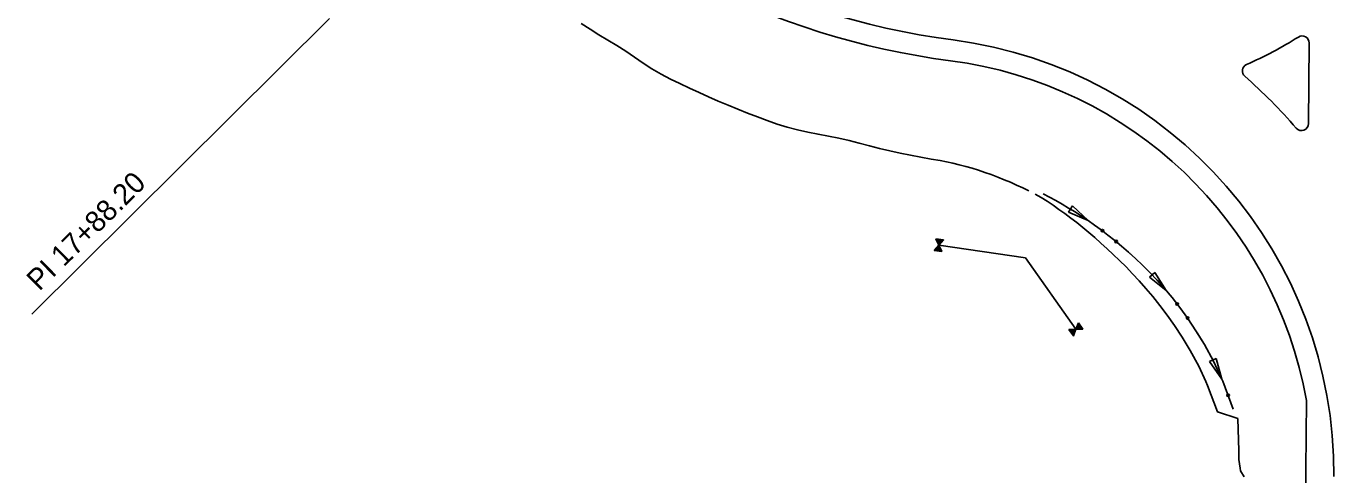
# Model space of a CAD drawing. Extents: x 1311167 to 1314552, y 2087587 to 2090602.
# Drawn here: x 1313604.5 to 1313978.4, y 2088279.1 to 2088407.4 of the extents above; entities that cross this region are included whole.
import ezdxf

# ---------------------------------------------------------------- set-up
doc = ezdxf.new("R2010")
doc.units = 0
for name, color, linetype in [('R_Shld_GR', 7, 'Continuous'), ('S_DITCHLINE', 7, 'Continuous'), ('S_DROP_INLET', 7, 'Continuous'), ('S_EDGE_CONCRETE', 7, 'Continuous'), ('S_EDGE_PAVEMENT', 7, 'Continuous'), ('S_PAVEMENT_CROWN', 7, 'Continuous')]:
    doc.layers.add(name, color=color, linetype=linetype)

msp = doc.modelspace()

# ---------------------------------------------------------------- linework, layer by layer
at = {"layer": 'R_Shld_GR'}
msp.add_lwpolyline([(1313691.22, 2088409.64), (1313606.07, 2088325.08)], dxfattribs=at)
at = {"layer": 'S_DITCHLINE'}
for p, q in [((1313903.72, 2088355.99), (1313902.57, 2088354.21)), ((1313902.57, 2088354.21), (1313908.19, 2088351.85)), ((1313908.19, 2088351.85), (1313903.72, 2088355.99)), ((1313927.27, 2088337.01), (1313925.69, 2088335.61)), ((1313925.69, 2088335.61), (1313930.47, 2088331.83)), ((1313930.47, 2088331.83), (1313927.27, 2088337.01)), ((1313944.81, 2088312.37), (1313942.89, 2088311.46)), ((1313946.42, 2088306.49), (1313944.81, 2088312.37)), ((1313942.89, 2088311.46), (1313946.42, 2088306.49))]:
    msp.add_line(p, q, dxfattribs=at)
for points in [[(1313895.28, 2088359.48), (1313897.1, 2088358.53), (1313898.92, 2088357.54), (1313900.75, 2088356.5), (1313902.58, 2088355.41), (1313904.43, 2088354.27), (1313906.29, 2088353.08), (1313908.16, 2088351.82), (1313910.04, 2088350.51), (1313911.94, 2088349.13), (1313913.85, 2088347.67), (1313915.78, 2088346.14), (1313917.73, 2088344.51), (1313919.71, 2088342.8), (1313921.7, 2088340.98), (1313923.73, 2088339.04), (1313925.78, 2088336.97), (1313927.87, 2088334.75), (1313929.99, 2088332.36), (1313932.16, 2088329.77), (1313934.38, 2088326.94), (1313936.66, 2088323.81), (1313939.01, 2088320.31), (1313941.44, 2088316.32), (1313943.99, 2088311.63), (1313946.17, 2088307.03), (1313946.68, 2088305.85), (1313949.63, 2088297.91)], [(1313895.28, 2088359.48), (1313897.1, 2088358.53), (1313898.92, 2088357.54), (1313900.75, 2088356.5), (1313902.58, 2088355.41), (1313904.43, 2088354.27), (1313906.29, 2088353.08), (1313908.16, 2088351.82), (1313908.17, 2088351.82)], [(1313919.96, 2088342.57), (1313919.99, 2088342.54)], [(1313919.99, 2088342.54), (1313921.7, 2088340.98), (1313923.73, 2088339.04), (1313925.78, 2088336.97), (1313927.87, 2088334.75), (1313929.99, 2088332.36), (1313930.46, 2088331.81)], [(1313939.35, 2088319.75), (1313939.37, 2088319.72)], [(1313939.37, 2088319.72), (1313941.44, 2088316.32), (1313943.99, 2088311.63), (1313946.17, 2088307.03), (1313946.4, 2088306.49)]]:
    msp.add_lwpolyline(points, dxfattribs=at)
for centre in [(1313912.26, 2088348.93), (1313916.2, 2088345.84), (1313933.64, 2088327.95), (1313936.62, 2088323.93), (1313948.21, 2088301.82)]:
    msp.add_circle(centre, 0.375, dxfattribs=at)
at = {"layer": 'S_DROP_INLET'}
for p, q in [((1313865.51, 2088344.78), (1313864.65, 2088346.59)), ((1313865.53, 2088344.81), (1313864.69, 2088346.58)), ((1313865.6, 2088344.92), (1313864.83, 2088346.56)), ((1313865.69, 2088344.99), (1313864.96, 2088346.54)), ((1313865.77, 2088345.09), (1313865.09, 2088346.52)), ((1313865.85, 2088345.17), (1313865.22, 2088346.5)), ((1313865.92, 2088345.28), (1313865.35, 2088346.48)), ((1313866.01, 2088345.35), (1313865.49, 2088346.46)), ((1313866.85, 2088346.26), (1313865.51, 2088344.78)), ((1313866.08, 2088345.46), (1313865.62, 2088346.44)), ((1313866.17, 2088345.54), (1313865.75, 2088346.42)), ((1313866.24, 2088345.65), (1313865.91, 2088346.34)), ((1313866.33, 2088345.71), (1313866.01, 2088346.39)), ((1313866.42, 2088345.79), (1313866.15, 2088346.37)), ((1313866.5, 2088345.88), (1313866.28, 2088346.35)), ((1313866.57, 2088345.98), (1313866.41, 2088346.33)), ((1313866.66, 2088346.06), (1313866.54, 2088346.31)), ((1313866.73, 2088346.16), (1313866.67, 2088346.29)), ((1313866.82, 2088346.24), (1313866.81, 2088346.27)), ((1313865.51, 2088344.78), (1313864.16, 2088343.29)), ((1313865.52, 2088344.73), (1313864.21, 2088343.28)), ((1313865.55, 2088344.61), (1313864.34, 2088343.26)), ((1313865.62, 2088344.52), (1313864.47, 2088343.24)), ((1313865.66, 2088344.4), (1313864.6, 2088343.22)), ((1313865.72, 2088344.3), (1313864.73, 2088343.2)), ((1313865.76, 2088344.17), (1313864.87, 2088343.19)), ((1313865.82, 2088344.08), (1313865, 2088343.17)), ((1313865.86, 2088343.96), (1313865.13, 2088343.15)), ((1313865.92, 2088343.85), (1313865.26, 2088343.13)), ((1313865.95, 2088343.73), (1313865.44, 2088343.16)), ((1313866.36, 2088342.96), (1313865.51, 2088344.78)), ((1313866.03, 2088343.64), (1313865.53, 2088343.09)), ((1313866.09, 2088343.54), (1313865.66, 2088343.07)), ((1313866.13, 2088343.43), (1313865.79, 2088343.05)), ((1313866.18, 2088343.31), (1313865.92, 2088343.03)), ((1313866.24, 2088343.21), (1313866.06, 2088343.01)), ((1313866.28, 2088343.09), (1313866.19, 2088342.99)), ((1313866.34, 2088342.99), (1313866.32, 2088342.97)), ((1313904.67, 2088320.71), (1313902.67, 2088320.65)), ((1313904.64, 2088320.67), (1313902.69, 2088320.62)), ((1313904.58, 2088320.56), (1313902.77, 2088320.51)), ((1313904.56, 2088320.45), (1313902.85, 2088320.4)), ((1313904.51, 2088320.33), (1313902.92, 2088320.29)), ((1313904.47, 2088320.22), (1313903, 2088320.18)), ((1313904.41, 2088320.11), (1313903.08, 2088320.07)), ((1313904.39, 2088320), (1313903.15, 2088319.96)), ((1313904.32, 2088319.89), (1313903.23, 2088319.86)), ((1313904.29, 2088319.77), (1313903.31, 2088319.75)), ((1313903.95, 2088318.84), (1313904.67, 2088320.71)), ((1313904.67, 2088320.71), (1313905.39, 2088322.58)), ((1313906.67, 2088320.76), (1313904.67, 2088320.71)), ((1313904.71, 2088320.72), (1313905.41, 2088322.54)), ((1313904.84, 2088320.74), (1313905.49, 2088322.43)), ((1313904.95, 2088320.73), (1313905.57, 2088322.32)), ((1313905.08, 2088320.74), (1313905.64, 2088322.22)), ((1313905.19, 2088320.73), (1313905.72, 2088322.11)), ((1313905.32, 2088320.76), (1313905.8, 2088322)), ((1313905.43, 2088320.74), (1313905.88, 2088321.89)), ((1313905.56, 2088320.76), (1313905.95, 2088321.78)), ((1313905.68, 2088320.76), (1313906.03, 2088321.67)), ((1313905.81, 2088320.78), (1313906.08, 2088321.49)), ((1313905.91, 2088320.75), (1313906.18, 2088321.45)), ((1313906.03, 2088320.75), (1313906.26, 2088321.34)), ((1313906.15, 2088320.76), (1313906.34, 2088321.23)), ((1313906.28, 2088320.77), (1313906.41, 2088321.13)), ((1313906.4, 2088320.76), (1313906.49, 2088321.02)), ((1313906.52, 2088320.78), (1313906.57, 2088320.91)), ((1313906.64, 2088320.77), (1313906.65, 2088320.8)), ((1313904.22, 2088319.66), (1313903.46, 2088319.64)), ((1313904.21, 2088319.55), (1313903.46, 2088319.53)), ((1313904.18, 2088319.44), (1313903.54, 2088319.42)), ((1313904.13, 2088319.32), (1313903.62, 2088319.31)), ((1313904.07, 2088319.21), (1313903.69, 2088319.2)), ((1313904.04, 2088319.1), (1313903.77, 2088319.09)), ((1313903.99, 2088318.99), (1313903.85, 2088318.98)), ((1313903.95, 2088318.87), (1313903.92, 2088318.87))]:
    msp.add_line(p, q, dxfattribs=at)
for points in [[(1313866.85, 2088346.26), (1313864.65, 2088346.59)], [(1313866.36, 2088342.96), (1313864.16, 2088343.29)], [(1313904.67, 2088320.71), (1313890.24, 2088341.12), (1313865.51, 2088344.78)], [(1313903.95, 2088318.84), (1313902.67, 2088320.65)], [(1313906.67, 2088320.76), (1313905.39, 2088322.58)]]:
    msp.add_lwpolyline(points, dxfattribs=at)
at = {"layer": 'S_EDGE_CONCRETE'}
for points in [[(1313891.24, 2088360.33), (1313889.48, 2088361.18), (1313887.71, 2088361.99), (1313885.95, 2088362.77), (1313884.18, 2088363.5), (1313882.33, 2088364.25), (1313880.48, 2088364.95), (1313878.64, 2088365.61), (1313876.81, 2088366.22), (1313874.98, 2088366.79), (1313873.15, 2088367.31), (1313871.32, 2088367.79), (1313869.49, 2088368.22), (1313867.66, 2088368.62), (1313865.82, 2088368.97), (1313863.3, 2088369.4), (1313860.33, 2088369.95), (1313857.37, 2088370.53), (1313854.42, 2088371.14), (1313851.48, 2088371.78), (1313848.55, 2088372.45), (1313845.62, 2088373.16), (1313842.71, 2088373.92), (1313839.81, 2088374.72), (1313836.88, 2088375.38), (1313833.92, 2088375.93), (1313830.96, 2088376.52), (1313828.01, 2088377.15), (1313825.07, 2088377.81), (1313822.12, 2088378.5), (1313819.25, 2088379.42), (1313816.41, 2088380.44), (1313813.58, 2088381.49), (1313810.77, 2088382.57), (1313807.97, 2088383.69), (1313805.18, 2088384.83), (1313802.4, 2088386), (1313799.64, 2088387.21), (1313796.89, 2088388.44), (1313794.15, 2088389.7), (1313791.43, 2088390.99), (1313788.72, 2088392.3), (1313786.03, 2088393.65), (1313783.44, 2088395.2), (1313780.9, 2088396.83), (1313778.39, 2088398.52), (1313775.93, 2088400.25), (1313773.43, 2088401.93), (1313770.83, 2088403.42), (1313768.27, 2088404.97), (1313765.73, 2088406.57), (1313763.23, 2088408.22)], [(1313892.99, 2088359.41), (1313894.71, 2088358.39), (1313896.43, 2088357.32), (1313898.14, 2088356.2), (1313899.84, 2088355.02), (1313901.54, 2088353.8), (1313903.25, 2088352.54), (1313904.95, 2088351.22), (1313906.66, 2088349.85), (1313908.38, 2088348.42), (1313910.1, 2088346.94), (1313911.79, 2088345.34), (1313913.58, 2088343.78), (1313915.38, 2088342.13), (1313917.19, 2088340.4), (1313919.02, 2088338.57), (1313920.87, 2088336.62), (1313922.74, 2088334.56), (1313924.66, 2088332.38), (1313926.65, 2088330.06), (1313928.67, 2088327.54), (1313930.73, 2088324.8), (1313932.85, 2088321.78), (1313935.05, 2088318.42), (1313937.37, 2088314.62), (1313939.8, 2088310.15), (1313941.87, 2088305.75), (1313942.35, 2088304.63)], [(1313942.35, 2088304.63), (1313945.14, 2088297.06), (1313950.95, 2088295.24)], [(1313952.83, 2088278.48), (1313951.77, 2088280.22), (1313951.62, 2088280.99), (1313951.3, 2088283.49), (1313951.23, 2088285.99), (1313950.95, 2088295.24)]]:
    msp.add_lwpolyline(points, dxfattribs=at)
at = {"layer": 'S_EDGE_PAVEMENT'}
msp.add_line((1313969.96, 2088215.85), (1313970.61, 2088300.36), dxfattribs=at)
for centre, radius, start, end in [((1313896.86, 2088613.85), 218.13, 184.1502, 262.6016), ((1313853.45, 2088279.53), 119, 10.0819, 82.6016)]:
    msp.add_arc(centre, radius, start, end, dxfattribs=at)
at = {"layer": 'S_PAVEMENT_CROWN'}
msp.add_line((1313971.21, 2088379.55), (1313971.39, 2088402.62), dxfattribs=at)
for centre, radius, start, end in [((1313896.86, 2088613.85), 212.13, 181.1378, 262.6016), ((1313853.45, 2088279.53), 125, 359.5625, 82.6016), ((1313907.14, 2088501.7), 115, 293.7516, 302.1415), ((1313969.39, 2088402.63), 2, 359.5625, 122.1415), ((1313954.27, 2088394.61), 2, 113.7516, 228.7787), ((1313853.45, 2088279.53), 151, 40.8304, 48.7787), ((1313969.21, 2088379.56), 2, 220.8304, 359.5625)]:
    msp.add_arc(centre, radius, start, end, dxfattribs=at)

# ---------------------------------------------------------------- texts
at = {"layer": 'R_Shld_GR'}
msp.add_text('PI 17+88.20', height=6, rotation=44.8, dxfattribs=at).set_placement((1313608.21, 2088331.44))

doc.saveas('drawing.dxf')
